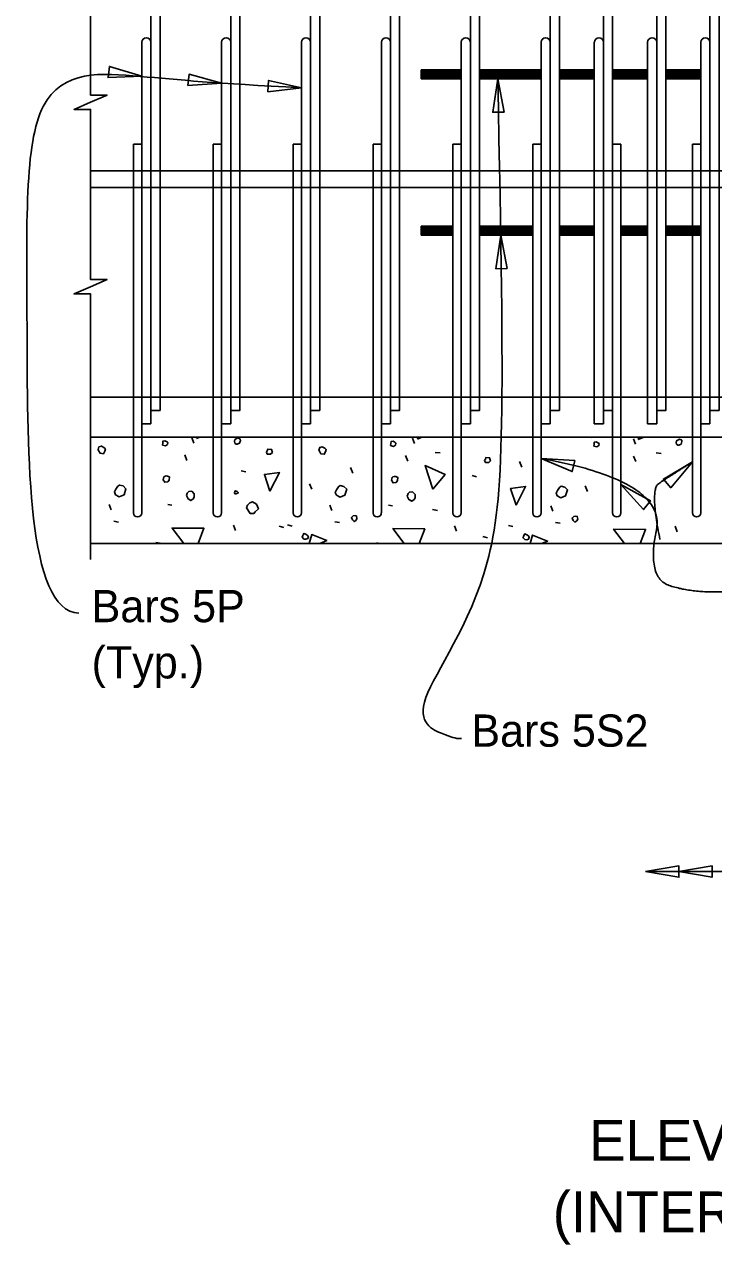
# Model space of a CAD drawing. Extents: x 120588.1 to 120659.6, y 120683.4 to 120715.5.
# Drawn here: x 120588.11 to 120592.42, y 120691.36 to 120699 of the extents above; entities that cross this region are included whole.
import ezdxf

# ---------------------------------------------------------------- set-up
doc = ezdxf.new("R2010")
doc.units = 0
for name, color, linetype in [('Dimension', 7, 'Continuous'), ('Patterning', 7, 'Continuous'), ('SheetBorder_dp', 7, 'Continuous'), ('SheetLines_dp', 7, 'Continuous'), ('SupstrConc', 7, 'Continuous')]:
    doc.layers.add(name, color=color, linetype=linetype)

msp = doc.modelspace()

# ---------------------------------------------------------------- linework, layer by layer
at = {"layer": 'Dimension'}
for p, q in [((120589.1671, 120696.383), (120589.1547, 120696.4166)), ((120590.2708, 120696.4203), (120590.2719, 120696.4201)), ((120590.5495, 120696.3795), (120590.5371, 120696.4131)), ((120591.6356, 120696.4203), (120591.6543, 120696.4166)), ((120591.9319, 120696.3759), (120591.9195, 120696.4095)), ((120589.1246, 120696.2734), (120589.1105, 120696.3088)), ((120590.507, 120696.2699), (120590.4929, 120696.3052)), ((120590.6785, 120696.3247), (120590.7103, 120696.3211)), ((120591.9339, 120696.2663), (120591.9197, 120696.3017)), ((120592.0609, 120696.3211), (120592.0927, 120696.3176)), ((120589.4641, 120696.2098), (120589.4923, 120696.2027)), ((120590.1623, 120696.1938), (120590.1482, 120696.2292)), ((120591.22, 120696.2313), (120591.2058, 120696.2667)), ((120589.906, 120696.0931), (120589.8919, 120696.1284)), ((120590.9093, 120696.1789), (120590.9376, 120696.1718)), ((120591.6313, 120696.0789), (120591.6172, 120696.1143)), ((120588.6491, 120695.964), (120588.6367, 120695.9976)), ((120589.0044, 120695.9976), (120589.0292, 120695.9941)), ((120590.0315, 120695.9605), (120590.0191, 120695.9941)), ((120590.3868, 120695.9941), (120590.4116, 120695.9906)), ((120590.6626, 120695.9658), (120590.6927, 120695.9605)), ((120591.4139, 120695.957), (120591.4015, 120695.9906)), ((120588.6668, 120695.8933), (120588.6968, 120695.888)), ((120590.0492, 120695.8898), (120590.0792, 120695.8845)), ((120589.4287, 120695.835), (120589.4163, 120695.8686)), ((120589.7027, 120695.8615), (120589.731, 120695.8544)), ((120589.754, 120695.8703), (120589.7823, 120695.8633)), ((120590.8111, 120695.8315), (120590.7987, 120695.865)), ((120591.1364, 120695.8668), (120591.1646, 120695.8597)), ((120591.4316, 120695.8863), (120591.4616, 120695.881)), ((120592.1935, 120695.8279), (120592.1811, 120695.8615)), ((120588.9302, 120695.7607), (120588.9567, 120695.7554)), ((120590.3126, 120695.7572), (120590.3303, 120695.7537)), ((120590.9772, 120695.7973), (120591.0054, 120695.7902))]:
    msp.add_line(p, q, dxfattribs=at)
for points in [[(120588.5713, 120696.3353), (120588.5802, 120696.3194), (120588.6014, 120696.3158), (120588.6102, 120696.3317), (120588.6138, 120696.3459), (120588.6049, 120696.3547), (120588.589, 120696.3636), (120588.5731, 120696.3582), (120588.5678, 120696.3423), (120588.5713, 120696.3353)], [(120588.9709, 120696.3706), (120588.9903, 120696.3653), (120589.0027, 120696.3742), (120589.0044, 120696.3865), (120589.0009, 120696.3901), (120588.9868, 120696.3971), (120588.9744, 120696.3954), (120588.9726, 120696.383), (120588.9709, 120696.3706)], [(120589.1848, 120696.4113), (120589.1875, 120696.4203)], [(120589.2049, 120696.4203), (120589.1848, 120696.4113)], [(120589.4322, 120696.3759), (120589.4393, 120696.3759), (120589.4535, 120696.383), (120589.4588, 120696.3989), (120589.457, 120696.4077), (120589.4428, 120696.4148), (120589.4252, 120696.4042), (120589.4216, 120696.3936), (120589.4252, 120696.383), (120589.4322, 120696.3759)], [(120589.9537, 120696.3317), (120589.9626, 120696.3158), (120589.9838, 120696.3123), (120589.9926, 120696.3282), (120589.9962, 120696.3423), (120589.9873, 120696.3512), (120589.9714, 120696.36), (120589.9555, 120696.3547), (120589.9502, 120696.3388), (120589.9537, 120696.3317)], [(120590.3987, 120696.3671), (120590.4181, 120696.3618), (120590.4305, 120696.3706), (120590.4322, 120696.383), (120590.4287, 120696.3865), (120590.4146, 120696.3936), (120590.4022, 120696.3918), (120590.4004, 120696.3795), (120590.3987, 120696.3671)], [(120590.5671, 120696.4077), (120590.571, 120696.4203)], [(120590.5952, 120696.4203), (120590.5671, 120696.4077)], [(120591.6712, 120696.3636), (120591.6907, 120696.3582), (120591.703, 120696.3671), (120591.7048, 120696.3795), (120591.7013, 120696.383), (120591.6871, 120696.3901), (120591.6747, 120696.3883), (120591.673, 120696.3759), (120591.6712, 120696.3636)], [(120591.9495, 120696.4042), (120591.9545, 120696.4203)], [(120591.9854, 120696.4203), (120591.9495, 120696.4042)], [(120592.197, 120696.3689), (120592.2041, 120696.3689), (120592.2182, 120696.3759), (120592.2235, 120696.3918), (120592.2218, 120696.4007), (120592.2076, 120696.4077), (120592.19, 120696.3971), (120592.1864, 120696.3865), (120592.19, 120696.3759), (120592.197, 120696.3689)], [(120589.6273, 120696.3131), (120589.6485, 120696.3131), (120589.6591, 120696.3237), (120589.6538, 120696.3431), (120589.6308, 120696.3449), (120589.6273, 120696.3343), (120589.622, 120696.3254), (120589.6273, 120696.3131), (120589.6237, 120696.3166)], [(120590.9924, 120696.2613), (120591.0137, 120696.2613), (120591.0243, 120696.2719), (120591.019, 120696.2913), (120590.996, 120696.2931), (120590.9924, 120696.2825), (120590.9871, 120696.2736), (120590.9924, 120696.2613), (120590.9889, 120696.2648)], [(120589.6427, 120696.0819), (120589.6091, 120696.1862), (120589.7028, 120696.1986), (120589.6427, 120696.0819)], [(120590.663, 120696.0949), (120590.6153, 120696.2416), (120590.7408, 120696.1868), (120590.663, 120696.0949)], [(120588.6774, 120696.0595), (120588.7004, 120696.0471), (120588.7304, 120696.0595), (120588.7428, 120696.0966), (120588.7251, 120696.1143), (120588.7022, 120696.1196), (120588.6915, 120696.1125), (120588.6792, 120696.0931), (120588.6703, 120696.0772), (120588.6774, 120696.0595)], [(120588.9762, 120696.1532), (120588.985, 120696.1373), (120589.0044, 120696.139), (120589.0133, 120696.1514), (120589.015, 120696.1709), (120589.0027, 120696.1762), (120588.9938, 120696.1779), (120588.9832, 120696.1744), (120588.9797, 120696.1709), (120588.9762, 120696.1532)], [(120590.4055, 120696.1497), (120590.4144, 120696.1337), (120590.4338, 120696.1355), (120590.4427, 120696.1479), (120590.4444, 120696.1673), (120590.432, 120696.1726), (120590.4232, 120696.1744), (120590.4126, 120696.1709), (120590.4091, 120696.1673), (120590.4055, 120696.1497)], [(120589.1211, 120696.0542), (120589.1317, 120696.033), (120589.1494, 120696.0224), (120589.1635, 120696.033), (120589.1706, 120696.0436), (120589.1706, 120696.0648), (120589.1547, 120696.0807), (120589.1353, 120696.0789), (120589.1264, 120696.0701), (120589.1211, 120696.0542)], [(120589.4269, 120696.063), (120589.4464, 120696.0719), (120589.4393, 120696.0789), (120589.4269, 120696.0842), (120589.4216, 120696.0719), (120589.4269, 120696.063)], [(120590.0598, 120696.056), (120590.0828, 120696.0436), (120590.1128, 120696.056), (120590.1252, 120696.0931), (120590.1075, 120696.1108), (120590.0845, 120696.1161), (120590.0739, 120696.109), (120590.0616, 120696.0895), (120590.0527, 120696.0736), (120590.0598, 120696.056)], [(120590.5035, 120696.0507), (120590.5141, 120696.0294), (120590.5318, 120696.0188), (120590.5459, 120696.0294), (120590.553, 120696.0401), (120590.553, 120696.0613), (120590.5371, 120696.0772), (120590.5176, 120696.0754), (120590.5088, 120696.0666), (120590.5035, 120696.0507)], [(120591.1844, 120695.9944), (120591.1508, 120696.0987), (120591.2445, 120696.1111), (120591.1844, 120695.9944)], [(120591.4422, 120696.0524), (120591.4652, 120696.0401), (120591.4952, 120696.0524), (120591.5076, 120696.0895), (120591.4899, 120696.1072), (120591.4669, 120696.1125), (120591.4563, 120696.1055), (120591.444, 120696.086), (120591.4351, 120696.0701), (120591.4422, 120696.0524)], [(120589.4976, 120695.9782), (120589.5206, 120695.9411), (120589.5436, 120695.9428), (120589.5524, 120695.9517), (120589.5719, 120695.9711), (120589.5595, 120696.0012), (120589.5348, 120696.0153), (120589.5171, 120696.0082), (120589.5029, 120695.9941), (120589.4976, 120695.9782)], [(120590.1606, 120695.9022), (120590.1712, 120695.8916), (120590.1818, 120695.8986), (120590.1888, 120695.9092), (120590.1853, 120695.9269), (120590.1765, 120695.9287), (120590.1641, 120695.9269), (120590.1535, 120695.9163), (120590.1606, 120695.9022)], [(120591.543, 120695.8986), (120591.5536, 120695.888), (120591.5642, 120695.8951), (120591.5712, 120695.9057), (120591.5677, 120695.9234), (120591.5589, 120695.9251), (120591.5465, 120695.9234), (120591.5359, 120695.9128), (120591.543, 120695.8986)], [(120589.1048, 120695.7537), (120589.031, 120695.8509), (120589.2307, 120695.8491), (120589.195, 120695.7537)], [(120589.8565, 120695.782), (120589.8689, 120695.7802), (120589.8813, 120695.7855), (120589.8848, 120695.7961), (120589.8795, 120695.8049), (120589.8689, 120695.812), (120589.8565, 120695.8173), (120589.8494, 120695.8032), (120589.8459, 120695.7926), (120589.8565, 120695.782)], [(120590.4846, 120695.7537), (120590.4133, 120695.8474), (120590.6131, 120695.8456), (120590.5788, 120695.7537)], [(120591.2389, 120695.7784), (120591.2513, 120695.7767), (120591.2636, 120695.782), (120591.2672, 120695.7926), (120591.2619, 120695.8014), (120591.2513, 120695.8085), (120591.2389, 120695.8138), (120591.2318, 120695.7996), (120591.2283, 120695.789), (120591.2389, 120695.7784)], [(120591.8643, 120695.7537), (120591.7957, 120695.8438), (120591.9955, 120695.8421), (120591.9625, 120695.7537)], [(120589.8886, 120695.7537), (120589.906, 120695.8102), (120589.9997, 120695.7731), (120589.9564, 120695.7537)], [(120591.2721, 120695.7537), (120591.2884, 120695.8067), (120591.3821, 120695.7696), (120591.3467, 120695.7537)]]:
    msp.add_lwpolyline(points, dxfattribs=at)
at = {"layer": 'SheetBorder_dp'}
for p, q in [((120588.5208, 120698.087), (120598.0015, 120698.087)), ((120588.5208, 120697.9829), (120598.0015, 120697.9829)), ((120588.5208, 120696.6703), (120598.0015, 120696.6703)), ((120588.5208, 120696.4203), (120607.6672, 120696.4203)), ((120588.5208, 120695.7537), (120607.6672, 120695.7537))]:
    msp.add_line(p, q, dxfattribs=at)
at = {"layer": 'SheetLines_dp'}
msp.add_line((120591.9958, 120693.7002), (120603.4029, 120693.7002), dxfattribs=at)
for points in [[(120588.5208, 120698.087), (120588.5208, 120698.4714), (120588.4174, 120698.4714), (120588.5208, 120698.5164), (120588.6241, 120698.5614), (120588.5208, 120698.5614), (120588.5208, 120699.087)], [(120588.5208, 120695.653), (120588.5208, 120697.3162), (120588.4174, 120697.3162), (120588.5208, 120697.3612), (120588.6241, 120697.4062), (120588.5208, 120697.4062), (120588.5208, 120698.087)]]:
    msp.add_lwpolyline(points, dxfattribs=at)
for points in [[(120588.8414, 120698.6792), (120588.6392, 120698.7404), (120588.6304, 120698.6704)], [(120589.3414, 120698.6363), (120589.1377, 120698.6921), (120589.1307, 120698.6219)], [(120589.8414, 120698.6076), (120589.6351, 120698.6531), (120589.6317, 120698.5826)], [(120591.0705, 120698.6624), (120591.0393, 120698.4535), (120591.1099, 120698.4549)], [(120591.0892, 120697.6833), (120591.0581, 120697.4744), (120591.1286, 120697.4758)], [(120591.3414, 120696.2866), (120591.5361, 120696.2047), (120591.5522, 120696.2734)], [(120592.2893, 120696.2643), (120592.1073, 120696.157), (120592.1528, 120696.1031)], [(120591.8414, 120696.1241), (120591.9817, 120695.9662), (120592.0259, 120696.0212)], [(120591.9958, 120693.7002), (120592.204, 120693.6649), (120592.204, 120693.7355)], [(120592.204, 120693.7002), (120592.4123, 120693.6649), (120592.4123, 120693.7355)]]:
    msp.add_lwpolyline(points, close=True, dxfattribs=at)
for points, degree in [([(120588.4481, 120695.3181), (120588.1208, 120695.3285), (120588.1335, 120697.2956), (120588.0935, 120698.7416), (120588.8414, 120698.6792), (120589.2991, 120698.6344), (120589.8414, 120698.6076)], 3), ([(120590.8438, 120694.5325), (120590.7997, 120694.5327), (120590.7647, 120694.5483), (120590.4614, 120694.6657), (120591.1134, 120695.5249), (120591.1127, 120696.5474), (120591.0705, 120698.6625)], 3), ([(120592.4772, 120695.4523), (120592.2948, 120695.4435), (120592.0006, 120695.5358), (120592.1255, 120696.1436), (120591.3414, 120696.2866)], 2), ([(120592.0858, 120695.7783), (120592.0228, 120696.09), (120592.13, 120696.166), (120592.2893, 120696.2643)], 2)]:
    msp.add_open_spline(points, degree=degree, dxfattribs=at)
at = {"layer": 'SupstrConc'}
for p, q in [((120588.8414, 120696.5037), (120588.8414, 120698.8917)), ((120588.8987, 120698.8917), (120588.8987, 120696.5037)), ((120589.3414, 120696.5037), (120589.3414, 120698.8917)), ((120589.3987, 120698.8917), (120589.3987, 120696.5037)), ((120589.8414, 120696.5037), (120589.8414, 120698.8917)), ((120589.8987, 120698.8917), (120589.8987, 120696.5037)), ((120590.3414, 120696.5037), (120590.3414, 120698.8917)), ((120590.3987, 120698.8917), (120590.3987, 120696.5037)), ((120590.8414, 120696.5037), (120590.8414, 120698.8917)), ((120590.8987, 120698.8917), (120590.8987, 120696.5037)), ((120591.3414, 120696.5037), (120591.3414, 120698.8917)), ((120591.3987, 120698.8917), (120591.3987, 120696.5037)), ((120591.6747, 120696.5037), (120591.6747, 120698.8917)), ((120591.732, 120698.8917), (120591.732, 120696.5037)), ((120592.008, 120696.5037), (120592.008, 120698.8917)), ((120592.0653, 120698.8917), (120592.0653, 120696.5037)), ((120592.3414, 120696.5037), (120592.3414, 120698.8917)), ((120592.3987, 120698.8917), (120592.3987, 120696.5037)), ((120590.5914, 120698.7198), (120590.8414, 120698.7198)), ((120590.5914, 120698.7198), (120590.5914, 120698.6625)), ((120590.956, 120698.7198), (120591.3414, 120698.7198)), ((120591.456, 120698.7198), (120591.6747, 120698.7198)), ((120591.7893, 120698.7198), (120592.008, 120698.7198)), ((120592.1226, 120698.7198), (120592.3414, 120698.7198)), ((120590.5914, 120698.7102), (120590.8414, 120698.7102)), ((120590.5914, 120698.7007), (120590.8414, 120698.7007)), ((120590.5914, 120698.6911), (120590.8414, 120698.6911)), ((120590.5914, 120698.6816), (120590.8414, 120698.6816)), ((120590.5914, 120698.672), (120590.8414, 120698.672)), ((120590.5914, 120698.6625), (120590.8414, 120698.6625)), ((120590.956, 120698.7102), (120591.3414, 120698.7102)), ((120590.956, 120698.7007), (120591.3414, 120698.7007)), ((120590.956, 120698.6911), (120591.3414, 120698.6911)), ((120590.956, 120698.6816), (120591.3414, 120698.6816)), ((120590.956, 120698.672), (120591.3414, 120698.672)), ((120590.956, 120698.6625), (120591.3414, 120698.6625)), ((120591.456, 120698.7102), (120591.6747, 120698.7102)), ((120591.456, 120698.7007), (120591.6747, 120698.7007)), ((120591.456, 120698.6911), (120591.6747, 120698.6911)), ((120591.456, 120698.6816), (120591.6747, 120698.6816)), ((120591.456, 120698.672), (120591.6747, 120698.672)), ((120591.456, 120698.6625), (120591.6747, 120698.6625)), ((120591.7893, 120698.7102), (120592.008, 120698.7102)), ((120591.7893, 120698.7007), (120592.008, 120698.7007)), ((120591.7893, 120698.6911), (120592.008, 120698.6911)), ((120591.7893, 120698.6816), (120592.008, 120698.6816)), ((120591.7893, 120698.672), (120592.008, 120698.672)), ((120591.7893, 120698.6625), (120592.008, 120698.6625)), ((120592.1226, 120698.7102), (120592.3414, 120698.7102)), ((120592.1226, 120698.7007), (120592.3414, 120698.7007)), ((120592.1226, 120698.6911), (120592.3414, 120698.6911)), ((120592.1226, 120698.6816), (120592.3414, 120698.6816)), ((120592.1226, 120698.672), (120592.3414, 120698.672)), ((120592.1226, 120698.6625), (120592.3414, 120698.6625)), ((120588.8414, 120698.2537), (120588.7893, 120698.2537)), ((120588.7893, 120698.2537), (120588.7893, 120695.9464)), ((120588.8414, 120695.9464), (120588.8414, 120698.2537)), ((120589.3414, 120698.2537), (120589.2893, 120698.2537)), ((120589.2893, 120698.2537), (120589.2893, 120695.9464)), ((120589.3414, 120695.9464), (120589.3414, 120698.2537)), ((120589.8414, 120698.2537), (120589.7893, 120698.2537)), ((120589.7893, 120698.2537), (120589.7893, 120695.9464)), ((120589.8414, 120695.9464), (120589.8414, 120698.2537)), ((120590.3414, 120698.2537), (120590.2893, 120698.2537)), ((120590.2893, 120698.2537), (120590.2893, 120695.9464)), ((120590.3414, 120695.9464), (120590.3414, 120698.2537)), ((120590.8414, 120698.2537), (120590.7893, 120698.2537)), ((120590.7893, 120698.2537), (120590.7893, 120695.9464)), ((120590.8414, 120695.9464), (120590.8414, 120698.2537)), ((120591.3414, 120698.2537), (120591.2893, 120698.2537)), ((120591.2893, 120698.2537), (120591.2893, 120695.9464)), ((120591.3414, 120695.9464), (120591.3414, 120698.2537)), ((120591.8414, 120698.2537), (120591.7893, 120698.2537)), ((120591.7893, 120698.2537), (120591.7893, 120695.9464)), ((120591.8414, 120695.9464), (120591.8414, 120698.2537)), ((120592.3414, 120698.2537), (120592.2893, 120698.2537)), ((120592.2893, 120698.2537), (120592.2893, 120695.9464)), ((120592.3414, 120695.9464), (120592.3414, 120698.2537)), ((120590.5914, 120697.7406), (120590.5914, 120697.6833)), ((120590.5914, 120697.7406), (120590.7893, 120697.7406)), ((120590.5914, 120697.7311), (120590.7893, 120697.7311)), ((120590.5914, 120697.7215), (120590.7893, 120697.7215)), ((120590.956, 120697.7406), (120591.2893, 120697.7406)), ((120590.956, 120697.7311), (120591.2893, 120697.7311)), ((120590.956, 120697.7215), (120591.2893, 120697.7215)), ((120591.456, 120697.7406), (120591.6747, 120697.7406)), ((120591.456, 120697.7311), (120591.6747, 120697.7311)), ((120591.456, 120697.7215), (120591.6747, 120697.7215)), ((120591.8414, 120697.7406), (120592.008, 120697.7406)), ((120591.8414, 120697.7311), (120592.008, 120697.7311)), ((120591.8414, 120697.7215), (120592.008, 120697.7215)), ((120592.1226, 120697.7406), (120592.3414, 120697.7406)), ((120592.1226, 120697.7311), (120592.3414, 120697.7311)), ((120592.1226, 120697.7215), (120592.3414, 120697.7215)), ((120590.5914, 120697.712), (120590.7893, 120697.712)), ((120590.5914, 120697.7024), (120590.7893, 120697.7024)), ((120590.5914, 120697.6929), (120590.7893, 120697.6929)), ((120590.5914, 120697.6833), (120590.7893, 120697.6833)), ((120590.956, 120697.712), (120591.2893, 120697.712)), ((120590.956, 120697.7024), (120591.2893, 120697.7024)), ((120590.956, 120697.6929), (120591.2893, 120697.6929)), ((120590.956, 120697.6833), (120591.2893, 120697.6833)), ((120591.456, 120697.712), (120591.6747, 120697.712)), ((120591.456, 120697.7024), (120591.6747, 120697.7024)), ((120591.456, 120697.6929), (120591.6747, 120697.6929)), ((120591.456, 120697.6833), (120591.6747, 120697.6833)), ((120591.8414, 120697.712), (120592.008, 120697.712)), ((120591.8414, 120697.7024), (120592.008, 120697.7024)), ((120591.8414, 120697.6929), (120592.008, 120697.6929)), ((120591.8414, 120697.6833), (120592.008, 120697.6833)), ((120592.1226, 120697.712), (120592.3414, 120697.712)), ((120592.1226, 120697.7024), (120592.3414, 120697.7024)), ((120592.1226, 120697.6929), (120592.3414, 120697.6929)), ((120592.1226, 120697.6833), (120592.3414, 120697.6833)), ((120588.8987, 120696.5037), (120588.8414, 120696.5037)), ((120589.3987, 120696.5037), (120589.3414, 120696.5037)), ((120589.8987, 120696.5037), (120589.8414, 120696.5037)), ((120590.3987, 120696.5037), (120590.3414, 120696.5037)), ((120590.8987, 120696.5037), (120590.8414, 120696.5037)), ((120591.3987, 120696.5037), (120591.3414, 120696.5037)), ((120591.732, 120696.5037), (120591.6747, 120696.5037)), ((120592.0653, 120696.5037), (120592.008, 120696.5037)), ((120592.3987, 120696.5037), (120592.3414, 120696.5037))]:
    msp.add_line(p, q, dxfattribs=at)
for points in [[(120588.8987, 120704.2537), (120588.956, 120704.2537), (120588.956, 120696.587), (120588.8987, 120696.587)], [(120589.3987, 120704.2537), (120589.456, 120704.2537), (120589.456, 120696.587), (120589.3987, 120696.587)], [(120589.8987, 120704.2537), (120589.956, 120704.2537), (120589.956, 120696.587), (120589.8987, 120696.587)], [(120590.3987, 120704.2537), (120590.456, 120704.2537), (120590.456, 120696.587), (120590.3987, 120696.587)], [(120590.8987, 120704.2537), (120590.956, 120704.2537), (120590.956, 120696.587), (120590.8987, 120696.587)], [(120591.3987, 120704.2537), (120591.456, 120704.2537), (120591.456, 120696.587), (120591.3987, 120696.587)], [(120591.732, 120704.2537), (120591.7893, 120704.2537), (120591.7893, 120696.587), (120591.732, 120696.587)], [(120592.0653, 120704.2537), (120592.1226, 120704.2537), (120592.1226, 120696.587), (120592.0653, 120696.587)], [(120592.3987, 120704.2537), (120592.456, 120704.2537), (120592.456, 120696.587), (120592.3987, 120696.587)]]:
    msp.add_lwpolyline(points, close=True, dxfattribs=at)
for centre, radius, start, end in [((120588.87, 120698.8917), 0.0286, 0, 180), ((120589.37, 120698.8917), 0.0286, 0, 180), ((120589.87, 120698.8917), 0.0286, 0, 180), ((120590.37, 120698.8917), 0.0286, 0, 180), ((120590.87, 120698.8917), 0.0286, 0, 180), ((120591.37, 120698.8917), 0.0286, 0, 180), ((120591.7034, 120698.8917), 0.0286, 0, 180), ((120592.0367, 120698.8917), 0.0286, 0, 180), ((120592.37, 120698.8917), 0.0286, 0, 180), ((120588.8153, 120695.9464), 0.026, 180, 0), ((120589.3153, 120695.9464), 0.026, 180, 0), ((120589.8153, 120695.9464), 0.026, 180, 0), ((120590.3153, 120695.9464), 0.026, 180, 0), ((120590.8153, 120695.9464), 0.026, 180, 0), ((120591.3153, 120695.9464), 0.026, 180, 0), ((120591.8153, 120695.9464), 0.026, 180, 0), ((120592.3153, 120695.9464), 0.026, 180, 0)]:
    msp.add_arc(centre, radius, start, end, dxfattribs=at)

# ---------------------------------------------------------------- texts
at = {"layer": 'Patterning'}
msp.add_text('Bars 5S2', height=0.2016, dxfattribs=at).set_placement((120590.9049, 120694.4819))
at = {"layer": 'SheetLines_dp'}
for s, height, p in [('Bars 5P', 0.2016, (120588.5276, 120695.2612)), ('(Typ.)', 0.2016, (120588.5276, 120694.9092)), ('ELEVATION OF RAILING/NOISE WALL REINFORCING STEEL ', 0.256001, (120591.6418, 120691.8899)), ('(INTERMEDIATE OPEN JOINT SHOWN, DECK JOINT SIMILAR) ', 0.256001, (120591.4145, 120691.4419))]:
    msp.add_text(s, height=height, dxfattribs=at).set_placement(p)

doc.saveas('drawing.dxf')
